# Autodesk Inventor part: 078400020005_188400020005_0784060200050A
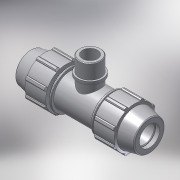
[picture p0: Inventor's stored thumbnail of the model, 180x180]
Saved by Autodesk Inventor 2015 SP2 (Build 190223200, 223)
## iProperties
Created: 2017-02
Part Number: 078400020005_188400020005_0784060200050A
Material: PVC-Piping
Description: PLASSON TEE WITH THREADED MALE OFFTAKE 20-1/2"-20
Document SubType Name: Modeling
Designer: KIM
Mass: 92.6774 g
Surface Area: 199.44 cm^2
Volume: 66.1981 cm^3
Density: 1.4 g/cm^3
Appearance: Smooth - White
Author: Кирилл
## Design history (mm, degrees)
derived "07840.ipt"
feature "Solid1::07840.ipt"
feature "Solid2::07840.ipt"
tag "TaggingFeature1"
body "Solid1"
body "Solid2"
other parameters: "d4" = 5.75, "d5" = 16.56, "d7" = 48, "d11" = 2.3, "d13" = 120 deg, "d15" = 12 deg, "d16" = 41.76, "d18" = 1, "d19" = 35 deg, "d20" = 17.5 deg, "d21" = 44.64, "d23" = 0, "d25" = 360 deg, "d27" = 0.96, "d33" = 0.4, "d42" = 24.84, "d43" = 1.44, "d46" = 0.6, "d68" = 2.3, "d72" = 46, "d73" = 20.955, "d74" = 17, "d75" = 24.09825, "d76" = 14.6685, "d77" = 20.4, "d80" = 0.62865, "d91" = 36, "d93" = 56, "d95" = 18, "d99" = 138, "d101" = 0, "d103" = 0, "d105" = 0, "E_" = 48, "A_" = 46, "l_" = 56, "l_2" = 17, "H_" = 138, "R_" = 20.955
